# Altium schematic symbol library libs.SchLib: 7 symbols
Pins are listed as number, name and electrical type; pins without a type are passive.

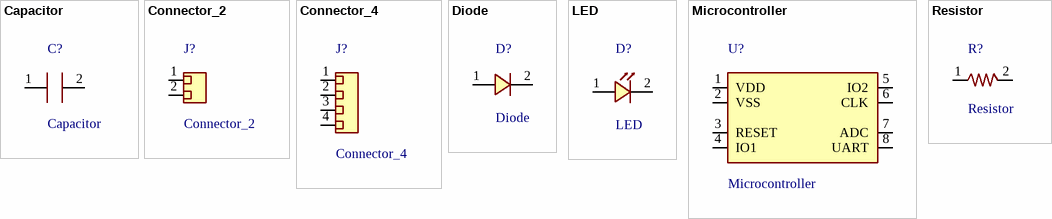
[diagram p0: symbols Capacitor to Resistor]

## Capacitor
designator C?
Generic non-polarized capacitor
pins: 1 A, 2 B

## Connector_2
designator J?
Generic two-circuit connector
pins: 1 Passive, 2 Passive

## Connector_4
designator J?
Generic four-circuit connector
pins: 1 Passive, 2 Passive, 3 Passive, 4 Passive

## Diode
designator D?
Generic two-terminal rectifier diode
pins: 1 A, 2 K

## LED
designator D?
Generic light-emitting diode
pins: 1 A, 2 K

## Microcontroller
designator U?
Conceptual controller block; not a device pinout
pins: 1 VDD, 2 VSS, 3 RESET, 4 IO1, 5 IO2, 6 CLK, 7 ADC, 8 UART

## Resistor
designator R?
Generic two-terminal resistor
pins: 1 A, 2 B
